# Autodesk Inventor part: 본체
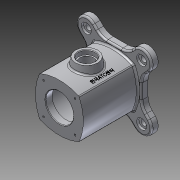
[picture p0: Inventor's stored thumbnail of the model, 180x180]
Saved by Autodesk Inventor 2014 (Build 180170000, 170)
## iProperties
Created: 2016-05
Part Number: 본체
Material: 알루미늄 6061
Document SubType Name: Modeling
Designer: J.H.CHAE
Density: 2.71 g/cm^3
Appearance: 알루미늄 - 평지
Mass: 1111.8 g
Surface Area: 864.181 cm^2
Volume: 410.257 cm^3
Author: J.H.CHAE
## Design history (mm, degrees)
sketch "스케치1"
  geometry: L1 (35.355, 35.355)-(-35.355, 35.355); L2 (-35.355, 35.355)-(-35.355, -35.355); L3 (-35.355, -35.355)-(35.355, -35.355); L4 (35.355, -35.355)-(35.355, 35.355); A1 r 85.579 centre (0, -42.579) between (35.355, 35.355) and (-35.355, 35.355); A2 r 85.579 centre (42.579, 0) between (-35.355, 35.355) and (-35.355, -35.355); A3 r 85.579 centre (0, 42.579) between (-35.355, -35.355) and (35.355, -35.355); A4 r 85.579 centre (-42.579, 0) between (35.355, -35.355) and (35.355, 35.355); 3 further points
  constraints: 9 end point, 8 point on circle, 4 centre point, 3 equal radius, 2 midpoint, 2 parallel, 2 perpendicular, 1 horizontal, 1 horizontal alignment, 1 vertical alignment
  dimensions: "d0" = 86 dimension on A2 A4; "d1" = 100 distance of L3.end L1.end
extrude "돌출1" new body sketch "스케치1" distance "d2" = 98; taper "d3" = 0 deg
sketch "스케치2"
  geometry: L1 (0, 0)-(-49.497, -49.497); L2 (0, 0)-(-70, 0); L3 (-49, -49)-(49, -49); L4 (49, -49)-(49, 49); L5 (49, 49)-(-49, 49); L6 (-49, 49)-(-49, -49); L7 (-49, -49)-(49, 49); L8 (49, -49)-(-49, 49); L9 (0, 98)-(0, -98) reference; L10 (62.225, -36.77)-(49, -23.544); L11 (36.77, -62.225)-(23.544, -49); L12 (62.225, 36.77)-(49, 23.544); L13 (36.77, 62.225)-(23.544, 49); L14 (-62.225, -36.77)-(-49, -23.544); L15 (-36.77, -62.225)-(-23.544, -49); L16 (-36.77, 62.225)-(-23.544, 49); L17 (-62.225, 36.77)-(-49, 23.544); A1 r 70 centre (0, 0) between (-49.497, -49.497) and (-70, 0); A2 r 18 centre (-49.497, -49.497) between (-36.77, -62.225) and (-62.225, -36.77); A3 r 18 centre (49.497, -49.497) between (62.225, -36.77) and (49, -31.504); A4 r 18 centre (49.497, 49.497) between (36.77, 62.225) and (62.225, 36.77); A5 r 18 centre (-49.497, 49.497) between (-62.225, 36.77) and (-36.77, 62.225); 9 further points
  constraints: 32 end point, 23 point on line, 17 symmetric about line, 11 point on circle, 5 centre point, 3 parallel, 2 coincident, 2 horizontal, 2 midpoint, 2 perpendicular, 1 tangent, 3 other
  dimensions: "d4" = 140 diameter of A1; "d5" = 45 deg angle of L1 L2; "d6" = 98 distance of L4.end L5.end; "d7" = 36 diameter of A2
extrude "돌출2" join sketch "스케치2" distance "d8" = 12; taper "d9" = 0 deg
sketch "스케치3"
  geometry: L1 (49, 55)-(69, 55); L2 (69, 55)-(69, 0); L3 (69, 0)-(49, 0); L4 (49, 0)-(49, 55); L5 (0, -35.355)-(0, 35.355) reference; L6 (-22, 0)-(132, 0) reference; 1 further point
  constraints: 8 end point, 2 parallel, 1 collinear, 1 horizontal, 1 perpendicular
  dimensions: "d12" = 55 distance from line of point (0, 0) L1; "d13" = 40 diameter of L2 L4; "d14" = 49 distance between parallel lines of L4 L5
revolve "회전1" sketch "스케치3" stored, may be unused: angle "d15" = 90 deg
sketch "스케치4"
  geometry: 1 further point
hole "구멍1" sketch "스케치4" at (0, 0) diameter "d16" = 50; stored, may be unused: countersink angle "d20" = 90 deg, drill point angle "d22" = 0 deg; dims "d17" = 6, "d18" = 4, "d19" = 2, "d21" = 12
hole "구멍2" diameter "d25" = 70; stored, may be unused: countersink angle "d29" = 90 deg, drill point angle "d31" = 0 deg; dims "d23" = 10, "d24" = 10, "d26" = 6, "d27" = 4, "d28" = 2, "d30" = 86
sketch "스케치5"
  geometry: 1 further point
hole "구멍3" sketch "스케치5" at (0, 0) diameter "d32" = 50; stored, may be unused: countersink angle "d36" = 90 deg, drill point angle "d38" = 0 deg; dims "d33" = 6, "d34" = 4, "d35" = 2, "d37" = 12
hole "구멍4" diameter "d41" = 10; stored, may be unused: countersink angle "d45" = 90 deg, drill point angle "d47" = 0 deg; dims "d39" = 10, "d40" = 10, "d42" = 6, "d43" = 18, "d44" = 4, "d46" = 12
sketch "스케치6" dims "d51" = 80
  geometry: L1 (0, 0)-(28.284, 28.284); L2 (-94.496, 0)-(94.496, 0) reference; 1 further point
  constraints: 2 end point, 1 coincident, 3 other
  dimensions: "d52" = 45 deg angle of L2 L1
hole "구멍5" sketch "스케치6" at (28.284, 28.284) diameter "d53" = 3.242; stored, may be unused: countersink angle "d57" = 90 deg, drill point angle "d59" = 118 deg; dims "d54" = 7, "d55" = 18, "d56" = 4, "d58" = 10
sketch "스케치7" dims "d63" = 80
  geometry: L1 (0, 0)-(-28.284, -28.284); L2 (-94.496, 0)-(94.496, 0) reference; 1 further point
  constraints: 2 end point, 1 coincident, 3 other
  dimensions: "d64" = 45 deg angle of L2 L1
hole "구멍6" sketch "스케치7" at (-28.284, -28.284) diameter "d65" = 3.242; stored, may be unused: countersink angle "d69" = 90 deg, drill point angle "d71" = 118 deg; dims "d66" = 7, "d67" = 18, "d68" = 4, "d70" = 10
hole "구멍7" diameter "d77" = 25; stored, may be unused: countersink angle "d81" = 90 deg, drill point angle "d83" = 0 deg; dims "d75" = 10, "d76" = 10, "d78" = 7, "d79" = 30, "d80" = 8, "d82" = 10
fillet "모깎기3" dims "d86" = 3
chamfer "모따기1" distance "d88" = 1; stored, may be unused: second distance "d89" = 2, angle "d90" = 45 deg
chamfer "모따기2" distance "d91" = 1; stored, may be unused: second distance "d92" = 2, angle "d93" = 45 deg
fillet "모깎기5" dims "d94" = 3
feature "면 기울기2" dims angle "d95" = 10 deg
fillet "모깎기6" dims "d96" = 3
fillet "모깎기7" dims "d97" = 3
sketch "스케치8"
  geometry: L1 (0, 0)-(29, 37.937); A1 r 85.579 centre (0, -42.579) between (34.285, 35.832) and (-34.285, 35.832) reference; A2 r 85.579 centre (-42.579, 0) between (35.832, -34.285) and (35.832, 34.285) reference
  constraints: 2 end point, 1 point on circle
  dimensions: "d98" = 29 horizontal distance of L1.start L1.end
fillet "모깎기8" dims "d104" = 25
fillet "모깎기9" dims "d105" = 3
node "작업 평면5"
sketch "스케치10"
  geometry: L1 (0, -5.686)-(0, 58.828) reference; 3 further points; 1 other entity
  constraints: 2 other
  dimensions: "d106" = 29 distance of point (49, 30.355) point (49, 1.355); "d107" = 49 distance from line of L1 point (49, 1.355)
feature "엠보싱2" sketch "스케치10" dims "d0" = 86, "d1" = 100, "d7" = 36, "d108" = 0.5, "d109" = 0
node "솔리드1"
pattern_circular "원형 패턴1" dims angle "d49" = 360 deg
pattern_circular "원형 패턴2" dims angle "d61" = 360 deg
pattern_circular "원형 패턴3" dims angle "d73" = 360 deg
